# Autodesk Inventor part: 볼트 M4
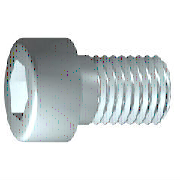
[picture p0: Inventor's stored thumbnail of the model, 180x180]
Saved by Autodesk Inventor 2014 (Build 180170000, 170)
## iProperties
IsCustomPart: 1
Created: 2012-02
Part Number: 볼트 M4
Material: 강철, 연강
Description: 6각머리 태핑 나사
Document SubType Name: Modeling
Standard: KS B 1003
Designer: mduedu
Standards Organization: KS
Language: ko-KR
Size Designation: M 4 x 12
Categories: <MemberInstance><Categories><Category DisplayName="조임쇠" InternalName="e4da775c-781d-43d5-af7c-5136215cf5a6" Mnemonic="FSTN"><Category DisplayName="볼트" InternalN
Density: 1 g/cm^3
Appearance: 강철
Author: mduedu
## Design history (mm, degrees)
sketch "스케치1"
  geometry: L1 (-1, 0)-(12, 0); L2 (12, 0)-(12, 2); L3 (12, 2)-(1.75, 2); L4 (1.75, 2)-(1.32, 2); L5 (1.32, 2)-(0, 2); L6 (0, 2)-(0, 3.5); L7 (0, 3.5)-(-4, 3.5); L8 (-4, 3.5)-(-4, 1.732); L9 (-4, 1.732)-(-2, 1.732); L10 (-2, 1.732)-(-1, 0); L11 (-7.2, 0)-(15.2, 0) reference; L12 (0, -0.7)-(0, 4.2) reference; L13 (1.75, 2)-(0, 2)
  constraints: 22 end point, 6 parallel, 2 collinear, 2 perpendicular, 1 horizontal, 1 point on line
  dimensions: "d1" = 10.25 distance from line of L3.end L2 (= GEL); "d2" = 0.42952 distance of L4.end L3.end (computed from GAL); "d3" = 4 distance between parallel lines of L8 L6 (= KOH); "d4" = 2 distance of L8.end L9.end (= INTI); "d5" = 60 deg angle of L10 L1; "d6" = 4 diameter of L3 L1 (= GD); "d7" = 4 diameter of L5 L1 (= BDM); "d8" = 3.4641 diameter of L9 L1 (= 1.1547 x SW); "d9" = 7 diameter of L7 L1 (= KOD); "d26" = 12 distance between parallel lines of L12 L2 (= NLG)
revolve "본체" sketch "스케치1" stored, may be unused: angle "d10" = 90 deg
sketch "스케치2"
  geometry: L1 (0, -4.9)-(0, 4.9) reference; L2 (-4.9, 0)-(4.9, 0) reference; L3 (1.732, 0)-(0.866, -1.5); L4 (0.866, -1.5)-(-0.866, -1.5); L5 (-0.866, -1.5)-(-1.732, 0); L6 (-1.732, 0)-(-0.866, 1.5); L7 (-0.866, 1.5)-(0.866, 1.5); L8 (0.866, 1.5)-(1.732, 0); 2 further points
  constraints: 12 end point, 1 coincident, 1 horizontal alignment, 1 point on line, 12 other
extrude "슬롯" join sketch "스케치2" stored distance "d11" = 10; taper "d12" = 0 deg
workplane "Work Plane1"
fillet "Fillet2" dims "d30" = 0.1 (= R)
body "Solid1"
fillet "모깎기1" dims "d17" = 0.4 (= RR)
feature "스레드" dims "d13" = 10.25 (= GEL), "d14" = 0
chamfer "모따기1" distance "d15" = 0.42941 (= -0.5 x SPD + 0.5 x GD); stored, may be unused: second distance "d16" = 0.42941 (= GUL), angle "d27" = 45 deg
other parameters: "GD" = 4 (= NND) [user parameter; used in 2 equation terms], "NLG" = 12 [user parameter; used in 1 equation term], "GEL" = 10.25 [user parameter; used in 2 equation terms], "KOD" = 7 [user parameter; used in 1 equation term], "KOH" = 4 [user parameter; used in 1 equation term], "INTI" = 2 [user parameter; used in 1 equation term], "GAL" = 0.42941 (= 0.61345 x PTC) [user parameter; used in 1 equation term], "GUL" = 0.42941 (= 0.61345 x PTC) [user parameter; used in 1 equation term], "BDM" = 4 (= NND) [user parameter; used in 1 equation term], "SW" = 3 [user parameter; used in 2 equation terms], "RR" = 0.4 [user parameter; used in 1 equation term], "SPD" = 3.14117 (= NND - 1.2269 x PTC) [user parameter; used in 1 equation term], "d19" = 0, "d28" = 0, "d29" = 0, "R" = 0.1 [user parameter; used in 1 equation term], "PHH" = 0.2 [user parameter], "GD1" = 3.14117 (= THREADDIA - 1.2269 x PTC) [user parameter], "THREADDIA" = 4 [user parameter; used in 1 equation term], "FAWI" = 45 deg [user parameter], "TPU" = 14.28571 (computed from PTC) [user parameter], "PTC" = 0.7 [user parameter; used in 5 equation terms], "NND" = 4 [user parameter; used in 3 equation terms], "TOA" = 30 deg [user parameter], "E0" = 3.465 (= 1.155 x SW) [user parameter]
